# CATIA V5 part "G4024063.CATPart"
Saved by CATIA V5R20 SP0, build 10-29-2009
Part number: G4024063
Revision: 3
Definition: design
Nomenclature: G4024063
Source: made
Description: NOT SPECIFIED
Bounding box of the stored display mesh (mm): x -25 to 63, y -28 to 28, z -28 to 28
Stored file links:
  C:\Users\Raffaele\Desktop\3D X SITO CF\BOLEX\26-BUSH REF 402\G4024063.CATPart
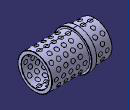
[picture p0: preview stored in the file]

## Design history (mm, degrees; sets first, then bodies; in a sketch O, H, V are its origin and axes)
Body1 "MANIFOLD_SOLID_BREP #15313" (main body)
  Solid1: solid without history
Body2 "MANIFOLD_SOLID_BREP #15472"
  Solid2: solid without history
Body3 "MANIFOLD_SOLID_BREP #15631"
  Solid3: solid without history
Body4 "MANIFOLD_SOLID_BREP #15792"
  Solid4: solid without history
Body5 "MANIFOLD_SOLID_BREP #15953"
  Solid5: solid without history
Body6 "MANIFOLD_SOLID_BREP #16114"
  Solid6: solid without history
Body7 "MANIFOLD_SOLID_BREP #16275"
  Solid7: solid without history
Body8 "MANIFOLD_SOLID_BREP #16436"
  Solid8: solid without history
Body9 "MANIFOLD_SOLID_BREP #16597"
  Solid9: solid without history
Body10 "MANIFOLD_SOLID_BREP #16758"
  Solid10: solid without history
Body11 "MANIFOLD_SOLID_BREP #16919"
  Solid11: solid without history
Body12 "MANIFOLD_SOLID_BREP #17080"
  Solid12: solid without history
Body13 "MANIFOLD_SOLID_BREP #17241"
  Solid13: solid without history
Body14 "MANIFOLD_SOLID_BREP #17402"
  Solid14: solid without history
Body15 "MANIFOLD_SOLID_BREP #17563"
  Solid15: solid without history
Body16 "MANIFOLD_SOLID_BREP #17724"
  Solid16: solid without history
Body17 "MANIFOLD_SOLID_BREP #17885"
  Solid17: solid without history
Body18 "MANIFOLD_SOLID_BREP #18046"
  Solid18: solid without history
Body19 "MANIFOLD_SOLID_BREP #18207"
  Solid19: solid without history
Body20 "MANIFOLD_SOLID_BREP #18368"
  Solid20: solid without history
Body21 "MANIFOLD_SOLID_BREP #18529"
  Solid21: solid without history
Body22 "MANIFOLD_SOLID_BREP #18690"
  Solid22: solid without history
Body23 "MANIFOLD_SOLID_BREP #18851"
  Solid23: solid without history
Body24 "MANIFOLD_SOLID_BREP #19010"
  Solid24: solid without history
Body25 "MANIFOLD_SOLID_BREP #19169"
  Solid25: solid without history
Body26 "MANIFOLD_SOLID_BREP #19330"
  Solid26: solid without history
Body27 "MANIFOLD_SOLID_BREP #19491"
  Solid27: solid without history
Body28 "MANIFOLD_SOLID_BREP #19652"
  Solid28: solid without history
Body29 "MANIFOLD_SOLID_BREP #19813"
  Solid29: solid without history
Body30 "MANIFOLD_SOLID_BREP #19974"
  Solid30: solid without history
Body31 "MANIFOLD_SOLID_BREP #20135"
  Solid31: solid without history
Body32 "MANIFOLD_SOLID_BREP #20294"
  Solid32: solid without history
Body33 "MANIFOLD_SOLID_BREP #20453"
  Solid33: solid without history
Body34 "MANIFOLD_SOLID_BREP #20614"
  Solid34: solid without history
Body35 "MANIFOLD_SOLID_BREP #20775"
  Solid35: solid without history
Body36 "MANIFOLD_SOLID_BREP #20936"
  Solid36: solid without history
Body37 "MANIFOLD_SOLID_BREP #21097"
  Solid37: solid without history
Body38 "MANIFOLD_SOLID_BREP #21258"
  Solid38: solid without history
Body39 "MANIFOLD_SOLID_BREP #21419"
  Solid39: solid without history
Body40 "MANIFOLD_SOLID_BREP #21580"
  Solid40: solid without history
Body41 "MANIFOLD_SOLID_BREP #21741"
  Solid41: solid without history
Body42 "MANIFOLD_SOLID_BREP #21902"
  Solid42: solid without history
Body43 "MANIFOLD_SOLID_BREP #22063"
  Solid43: solid without history
Body44 "MANIFOLD_SOLID_BREP #22224"
  Solid44: solid without history
Body45 "MANIFOLD_SOLID_BREP #22385"
  Solid45: solid without history
Body46 "MANIFOLD_SOLID_BREP #22546"
  Solid46: solid without history
Body47 "MANIFOLD_SOLID_BREP #22707"
  Solid47: solid without history
Body48 "MANIFOLD_SOLID_BREP #22868"
  Solid48: solid without history
Body49 "MANIFOLD_SOLID_BREP #23029"
  Solid49: solid without history
Body50 "MANIFOLD_SOLID_BREP #23190"
  Solid50: solid without history
Body51 "MANIFOLD_SOLID_BREP #23351"
  Solid51: solid without history
Body52 "MANIFOLD_SOLID_BREP #23512"
  Solid52: solid without history
Body53 "MANIFOLD_SOLID_BREP #23673"
  Solid53: solid without history
Body54 "MANIFOLD_SOLID_BREP #23832"
  Solid54: solid without history
Body55 "MANIFOLD_SOLID_BREP #23991"
  Solid55: solid without history
Body56 "MANIFOLD_SOLID_BREP #24150"
  Solid56: solid without history
Body57 "MANIFOLD_SOLID_BREP #24309"
  Solid57: solid without history
Body58 "MANIFOLD_SOLID_BREP #24470"
  Solid58: solid without history
Body59 "MANIFOLD_SOLID_BREP #24631"
  Solid59: solid without history
Body60 "MANIFOLD_SOLID_BREP #24792"
  Solid60: solid without history
Body61 "MANIFOLD_SOLID_BREP #24953"
  Solid61: solid without history
Body62 "MANIFOLD_SOLID_BREP #25114"
  Solid62: solid without history
Body63 "MANIFOLD_SOLID_BREP #25275"
  Solid63: solid without history
Body64 "MANIFOLD_SOLID_BREP #25436"
  Solid64: solid without history
Body65 "MANIFOLD_SOLID_BREP #25597"
  Solid65: solid without history
Body66 "MANIFOLD_SOLID_BREP #25758"
  Solid66: solid without history
Body67 "MANIFOLD_SOLID_BREP #25919"
  Solid67: solid without history
Body68 "MANIFOLD_SOLID_BREP #26080"
  Solid68: solid without history
Body69 "MANIFOLD_SOLID_BREP #26241"
  Solid69: solid without history
Body70 "MANIFOLD_SOLID_BREP #26402"
  Solid70: solid without history
Body71 "MANIFOLD_SOLID_BREP #26563"
  Solid71: solid without history
Body72 "MANIFOLD_SOLID_BREP #26724"
  Solid72: solid without history
Body73 "MANIFOLD_SOLID_BREP #26885"
  Solid73: solid without history
Body74 "MANIFOLD_SOLID_BREP #27046"
  Solid74: solid without history
Body75 "MANIFOLD_SOLID_BREP #27207"
  Solid75: solid without history
Body76 "MANIFOLD_SOLID_BREP #27368"
  Solid76: solid without history
Body77 "MANIFOLD_SOLID_BREP #27529"
  Solid77: solid without history
Body78 "MANIFOLD_SOLID_BREP #27688"
  Solid78: solid without history
Body79 "MANIFOLD_SOLID_BREP #27847"
  Solid79: solid without history
Body80 "MANIFOLD_SOLID_BREP #28006"
  Solid80: solid without history
Body81 "MANIFOLD_SOLID_BREP #28165"
  Solid81: solid without history
Body82 "MANIFOLD_SOLID_BREP #28326"
  Solid82: solid without history
Body83 "MANIFOLD_SOLID_BREP #28487"
  Solid83: solid without history
Body84 "MANIFOLD_SOLID_BREP #28648"
  Solid84: solid without history
Body85 "MANIFOLD_SOLID_BREP #28809"
  Solid85: solid without history
Body86 "MANIFOLD_SOLID_BREP #28970"
  Solid86: solid without history
Body87 "MANIFOLD_SOLID_BREP #29131"
  Solid87: solid without history
Body88 "MANIFOLD_SOLID_BREP #29292"
  Solid88: solid without history
Body89 "MANIFOLD_SOLID_BREP #29453"
  Solid89: solid without history
Body90 "MANIFOLD_SOLID_BREP #29614"
  Solid90: solid without history
Body91 "MANIFOLD_SOLID_BREP #29775"
  Solid91: solid without history
Body92 "MANIFOLD_SOLID_BREP #29936"
  Solid92: solid without history
Body93 "MANIFOLD_SOLID_BREP #30097"
  Solid93: solid without history
Body94 "MANIFOLD_SOLID_BREP #30258"
  Solid94: solid without history
Body95 "MANIFOLD_SOLID_BREP #30419"
  Solid95: solid without history
Body96 "MANIFOLD_SOLID_BREP #30580"
  Solid96: solid without history
Body97 "MANIFOLD_SOLID_BREP #30741"
  Solid97: solid without history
